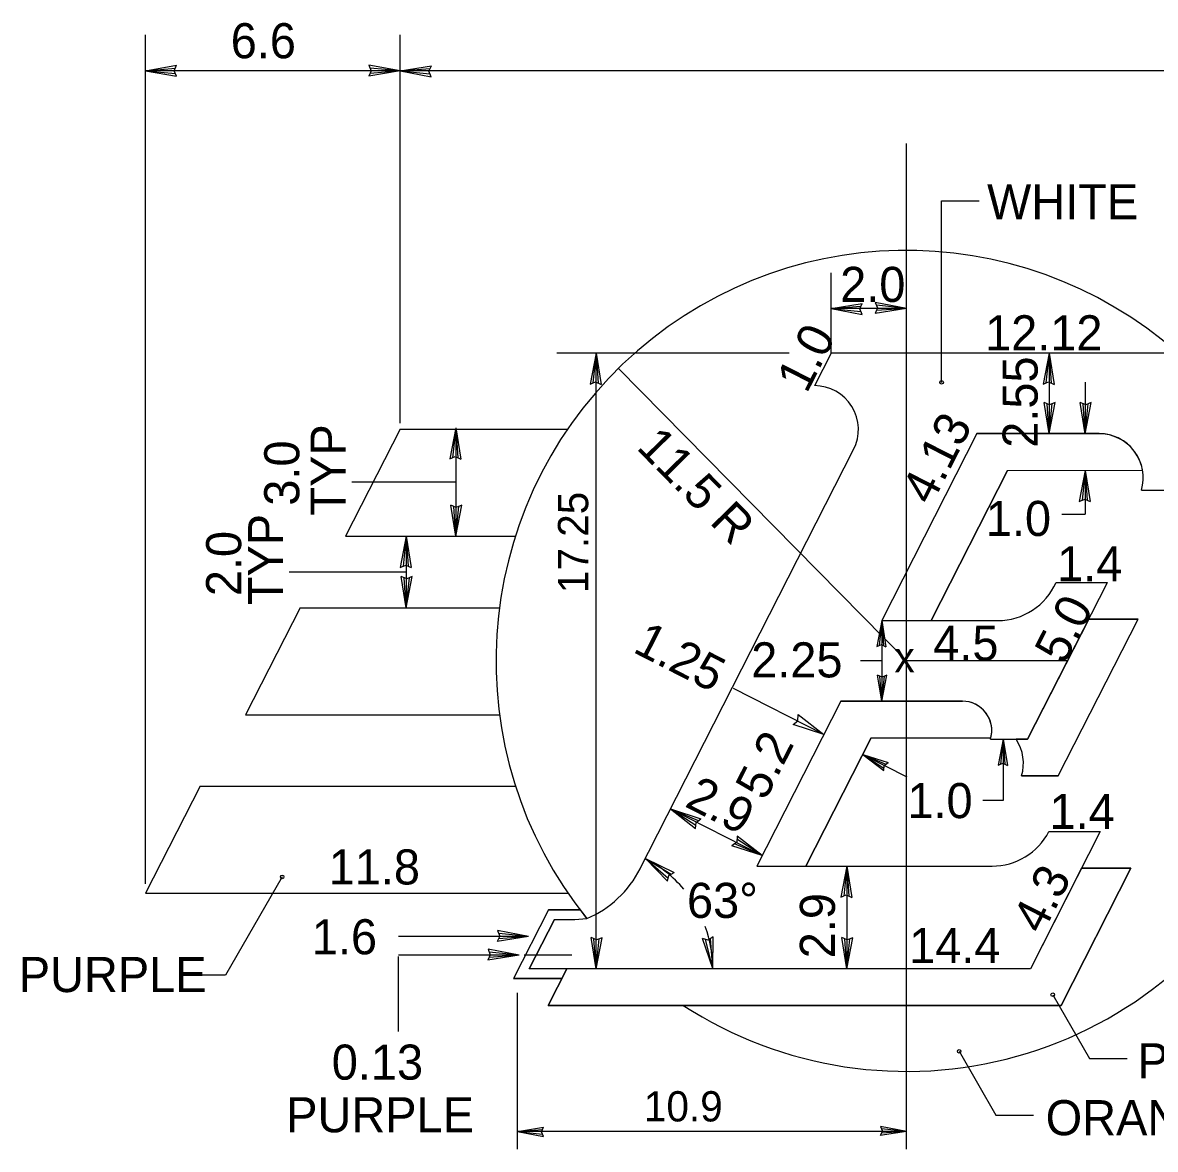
# Model space of a CAD drawing. Extents: x 10268197 to 10269179, y 2141503 to 2142677.
# Drawn here: x 10268648.48 to 10268671.08, y 2142115.25 to 2142137.72 of the extents above; entities that cross this region are included whole.
import ezdxf

# ---------------------------------------------------------------- set-up
doc = ezdxf.new("R2010")
doc.units = 0
for name, color, linetype in [('1', 7, 'Continuous'), ('2', 7, 'Continuous'), ('20', 7, 'Continuous'), ('21', 7, 'Continuous'), ('3', 7, 'Continuous'), ('52', 7, 'Continuous')]:
    doc.layers.add(name, color=color, linetype=linetype)

msp = doc.modelspace()

# ---------------------------------------------------------------- linework, layer by layer
at = {"layer": '1'}
for p, q in [((10268666.115, 2142124.99), (10268666.116, 2142135.313)), ((10268664.613, 2142131.13), (10268664.281, 2142130.479)), ((10268673.238, 2142131.13), (10268664.613, 2142131.13)), ((10268666.115, 2142124.99), (10268660.37, 2142130.823)), ((10268656.016, 2142129.611), (10268654.928, 2142127.475)), ((10268656.016, 2142129.611), (10268659.357, 2142129.611)), ((10268667.523, 2142129.523), (10268665.624, 2142125.794)), ((10268667.523, 2142129.523), (10268665.624, 2142125.794)), ((10268667.523, 2142129.523), (10268669.963, 2142129.523)), ((10268669.963, 2142129.523), (10268667.523, 2142129.523)), ((10268660.785, 2142120.807), (10268665.064, 2142129.204)), ((10268668.135, 2142128.791), (10268666.608, 2142125.794)), ((10268666.608, 2142125.794), (10268668.135, 2142128.791)), ((10268668.135, 2142128.791), (10268670.829, 2142128.792)), ((10268668.135, 2142128.791), (10268670.829, 2142128.792)), ((10268657.126, 2142128.557), (10268655.055, 2142128.557)), ((10268670.804, 2142128.395), (10268671.844, 2142128.396)), ((10268654.928, 2142127.475), (10268658.315, 2142127.475)), ((10268656.138, 2142126.763), (10268653.801, 2142126.763)), ((10268668.534, 2142123.427), (10268670.127, 2142126.554)), ((10268669.102, 2142126.554), (10268670.127, 2142126.554)), ((10268654.02, 2142126.051), (10268652.931, 2142123.916)), ((10268654.02, 2142126.051), (10268657.998, 2142126.051)), ((10268665.624, 2142125.794), (10268667.937, 2142125.794)), ((10268665.624, 2142125.794), (10268666.608, 2142125.794)), ((10268669.754, 2142125.822), (10268668.534, 2142123.427)), ((10268669.146, 2142122.696), (10268670.739, 2142125.823)), ((10268669.146, 2142122.696), (10268670.739, 2142125.823)), ((10268669.754, 2142125.822), (10268670.739, 2142125.823)), ((10268670.739, 2142125.823), (10268669.754, 2142125.822)), ((10268665.624, 2142124.99), (10268665.199, 2142124.99)), ((10268666.116, 2142115.249), (10268666.115, 2142124.99)), ((10268669.33, 2142124.99), (10268666.115, 2142124.99)), ((10268664.805, 2142124.186), (10268663.129, 2142120.897)), ((10268664.805, 2142124.186), (10268663.129, 2142120.897)), ((10268664.805, 2142124.186), (10268667.236, 2142124.186)), ((10268667.236, 2142124.186), (10268664.805, 2142124.186)), ((10268652.931, 2142123.916), (10268657.999, 2142123.916)), ((10268665.416, 2142123.455), (10268664.113, 2142120.897)), ((10268664.113, 2142120.897), (10268665.416, 2142123.455)), ((10268665.416, 2142123.455), (10268667.802, 2142123.455)), ((10268665.416, 2142123.455), (10268667.802, 2142123.455)), ((10268667.794, 2142123.427), (10268668.534, 2142123.427)), ((10268668.534, 2142123.427), (10268668.307, 2142123.427)), ((10268669.146, 2142122.696), (10268668.414, 2142122.696)), ((10268668.414, 2142122.696), (10268669.146, 2142122.696)), ((10268652.025, 2142122.492), (10268650.935, 2142120.356)), ((10268652.025, 2142122.492), (10268658.319, 2142122.492)), ((10268669.984, 2142121.585), (10268668.59, 2142118.85)), ((10268668.96, 2142121.585), (10268669.984, 2142121.585)), ((10268663.129, 2142120.897), (10268667.825, 2142120.897)), ((10268663.129, 2142120.897), (10268664.113, 2142120.897)), ((10268669.611, 2142120.854), (10268668.59, 2142118.85)), ((10268670.595, 2142120.854), (10268669.201, 2142118.119)), ((10268669.201, 2142118.119), (10268670.595, 2142120.854)), ((10268669.611, 2142120.854), (10268670.595, 2142120.854)), ((10268670.595, 2142120.854), (10268669.611, 2142120.854)), ((10268650.935, 2142120.356), (10268659.366, 2142120.356)), ((10268668.59, 2142118.85), (10268658.593, 2142118.85)), ((10268658.967, 2142118.119), (10268659.339, 2142118.85)), ((10268659.339, 2142118.85), (10268658.967, 2142118.119)), ((10268668.59, 2142118.85), (10268659.339, 2142118.85)), ((10268659.24, 2142118.655), (10268658.275, 2142118.655)), ((10268658.356, 2142115.249), (10268658.356, 2142118.368)), ((10268669.201, 2142118.119), (10268658.967, 2142118.119)), ((10268658.967, 2142118.119), (10268669.201, 2142118.119))]:
    msp.add_line(p, q, dxfattribs=at)
for centre, radius, start, end in [((10268666.115, 2142124.99), 8.187, 48.5904, 218.8792), ((10268664.282, 2142129.603), 0.877, 333.0033, 90.1042), ((10268669.964, 2142128.645), 0.877, 343.4611, 90), ((10268669.964, 2142128.645), 0.877, 9.5941, 90), ((10268667.937, 2142127.066), 1.272, 270, 336.2493), ((10268667.235, 2142123.602), 0.585, 342.6625, 90), ((10268667.235, 2142123.602), 0.585, 345.5225, 90), ((10268667.574, 2142122.946), 0.877, 343.4611, 33.2756), ((10268667.574, 2142122.946), 0.877, 343.4611, 33.2756), ((10268667.825, 2142122.176), 1.279, 270, 332.5096), ((10268666.115, 2142124.99), 8.187, 237.0648, 334.1734), ((10268658.902, 2142121.815), 2.136, 293.1567, 333.0112)]:
    msp.add_arc(centre, radius, start, end, dxfattribs=at)
at = {"layer": '2'}
for p, q in [((10268658.974, 2142120.028), (10268658.275, 2142118.655)), ((10268658.974, 2142120.028), (10268659.611, 2142120.028)), ((10268659.093, 2142119.833), (10268658.593, 2142118.85))]:
    msp.add_line(p, q, dxfattribs=at)
at = {"layer": '20'}
for p, q in [((10268650.935, 2142120.546), (10268650.935, 2142137.474)), ((10268656.016, 2142130.772), (10268656.015, 2142137.474)), ((10268656.015, 2142136.761), (10268650.935, 2142136.761)), ((10268703.052, 2142136.761), (10268656.015, 2142136.761)), ((10268666.818, 2142134.168), (10268667.568, 2142134.169)), ((10268666.818, 2142130.546), (10268666.818, 2142134.168)), ((10268664.613, 2142131.13), (10268664.613, 2142132.732)), ((10268666.115, 2142132.021), (10268664.613, 2142132.021)), ((10268663.776, 2142131.13), (10268659.144, 2142131.13)), ((10268659.925, 2142118.85), (10268659.925, 2142131.13)), ((10268668.964, 2142131.13), (10268668.964, 2142129.523)), ((10268656.016, 2142129.735), (10268656.016, 2142130.772)), ((10268669.683, 2142130.549), (10268669.683, 2142129.522)), ((10268657.126, 2142129.638), (10268657.126, 2142127.475)), ((10268669.683, 2142128.791), (10268669.683, 2142127.915)), ((10268669.219, 2142127.915), (10268669.683, 2142127.915)), ((10268656.137, 2142127.475), (10268656.138, 2142126.051)), ((10268665.624, 2142125.794), (10268665.625, 2142124.186)), ((10268664.468, 2142123.524), (10268662.668, 2142124.441)), ((10268668.048, 2142123.427), (10268668.048, 2142122.204)), ((10268665.249, 2142123.126), (10268666.124, 2142122.68)), ((10268668.048, 2142122.204), (10268667.64, 2142122.204)), ((10268661.413, 2142122.038), (10268663.237, 2142121.108)), ((10268664.927, 2142120.897), (10268664.927, 2142118.85)), ((10268653.662, 2142120.682), (10268652.53, 2142118.721)), ((10268658.579, 2142119.491), (10268655.981, 2142119.491)), ((10268655.981, 2142117.599), (10268655.981, 2142119.095)), ((10268658.389, 2142119.118), (10268655.982, 2142119.119)), ((10268659.44, 2142119.119), (10268658.493, 2142119.119)), ((10268652.53, 2142118.721), (10268651.78, 2142118.72)), ((10268669.036, 2142118.332), (10268669.771, 2142117.06)), ((10268667.169, 2142117.204), (10268667.903, 2142115.932)), ((10268669.771, 2142117.06), (10268670.52, 2142117.061)), ((10268667.903, 2142115.932), (10268668.653, 2142115.932)), ((10268666.116, 2142115.606), (10268658.356, 2142115.606))]:
    msp.add_line(p, q, dxfattribs=at)
for centre in [(10268666.818, 2142130.546), (10268653.662, 2142120.682), (10268669.036, 2142118.332), (10268667.169, 2142117.204)]:
    msp.add_circle(centre, 0.0356, dxfattribs=at)
for start, end in [(40.0298, 62.999), (0, 19.9667)]:
    msp.add_arc((10268659.788, 2142118.85), 2.465, start, end, dxfattribs=at)
at = {"layer": '21'}
for p, q in [((10268650.935, 2142136.761), (10268651.557, 2142136.871)), ((10268650.935, 2142136.761), (10268651.532, 2142136.814)), ((10268651.509, 2142136.761), (10268651.557, 2142136.871)), ((10268656.015, 2142136.761), (10268655.394, 2142136.871)), ((10268655.394, 2142136.871), (10268655.441, 2142136.761)), ((10268656.015, 2142136.761), (10268655.418, 2142136.814)), ((10268656.015, 2142136.761), (10268656.639, 2142136.861)), ((10268656.59, 2142136.752), (10268656.639, 2142136.861)), ((10268650.935, 2142136.761), (10268651.557, 2142136.652)), ((10268650.935, 2142136.761), (10268651.532, 2142136.709)), ((10268651.557, 2142136.652), (10268651.509, 2142136.761)), ((10268656.015, 2142136.761), (10268655.393, 2142136.652)), ((10268655.441, 2142136.761), (10268655.393, 2142136.652)), ((10268656.015, 2142136.761), (10268655.419, 2142136.709)), ((10268656.015, 2142136.761), (10268656.612, 2142136.803)), ((10268656.015, 2142136.761), (10268656.635, 2142136.641)), ((10268656.015, 2142136.761), (10268656.611, 2142136.699)), ((10268656.635, 2142136.641), (10268656.59, 2142136.752)), ((10268664.613, 2142132.021), (10268665.237, 2142132.12)), ((10268665.187, 2142132.011), (10268665.237, 2142132.12)), ((10268666.115, 2142132.021), (10268665.496, 2142132.141)), ((10268665.496, 2142132.141), (10268665.541, 2142132.031)), ((10268666.115, 2142132.021), (10268665.519, 2142132.083)), ((10268664.613, 2142132.021), (10268665.21, 2142132.063)), ((10268664.613, 2142132.021), (10268665.233, 2142131.9)), ((10268664.613, 2142132.021), (10268665.209, 2142131.959)), ((10268665.233, 2142131.9), (10268665.187, 2142132.011)), ((10268665.541, 2142132.031), (10268665.492, 2142131.922)), ((10268666.115, 2142132.021), (10268665.492, 2142131.922)), ((10268666.115, 2142132.021), (10268665.518, 2142131.979)), ((10268659.925, 2142131.13), (10268659.805, 2142130.51)), ((10268659.925, 2142131.13), (10268659.863, 2142130.534)), ((10268659.925, 2142131.13), (10268660.024, 2142130.506)), ((10268659.925, 2142131.13), (10268659.967, 2142130.533)), ((10268668.964, 2142131.13), (10268668.844, 2142130.51)), ((10268668.964, 2142131.13), (10268668.901, 2142130.534)), ((10268668.964, 2142131.13), (10268669.063, 2142130.506)), ((10268668.964, 2142131.13), (10268669.006, 2142130.533)), ((10268659.805, 2142130.51), (10268659.915, 2142130.556)), ((10268659.915, 2142130.556), (10268660.024, 2142130.506)), ((10268668.844, 2142130.51), (10268668.954, 2142130.556)), ((10268668.954, 2142130.556), (10268669.063, 2142130.506)), ((10268668.964, 2142129.523), (10268668.865, 2142130.146)), ((10268668.974, 2142130.097), (10268668.865, 2142130.146)), ((10268668.964, 2142129.523), (10268668.922, 2142130.12)), ((10268668.964, 2142129.523), (10268669.084, 2142130.142)), ((10268668.964, 2142129.523), (10268669.026, 2142130.119)), ((10268669.084, 2142130.142), (10268668.974, 2142130.097)), ((10268669.683, 2142129.522), (10268669.584, 2142130.146)), ((10268669.693, 2142130.097), (10268669.584, 2142130.146)), ((10268669.683, 2142129.522), (10268669.641, 2142130.12)), ((10268669.683, 2142129.522), (10268669.803, 2142130.142)), ((10268669.683, 2142129.522), (10268669.745, 2142130.118)), ((10268669.803, 2142130.142), (10268669.693, 2142130.097)), ((10268657.126, 2142129.638), (10268657.006, 2142129.018)), ((10268657.126, 2142129.638), (10268657.063, 2142129.042)), ((10268657.126, 2142129.638), (10268657.225, 2142129.014)), ((10268657.126, 2142129.638), (10268657.168, 2142129.041)), ((10268657.006, 2142129.018), (10268657.116, 2142129.064)), ((10268657.116, 2142129.064), (10268657.225, 2142129.014)), ((10268669.683, 2142128.791), (10268669.563, 2142128.172)), ((10268669.683, 2142128.791), (10268669.621, 2142128.195)), ((10268669.683, 2142128.791), (10268669.782, 2142128.168)), ((10268669.683, 2142128.791), (10268669.725, 2142128.194)), ((10268657.126, 2142127.475), (10268657.027, 2142128.099)), ((10268657.136, 2142128.049), (10268657.027, 2142128.099)), ((10268657.126, 2142127.475), (10268657.084, 2142128.072)), ((10268657.126, 2142127.475), (10268657.247, 2142128.095)), ((10268657.126, 2142127.475), (10268657.188, 2142128.071)), ((10268657.247, 2142128.095), (10268657.136, 2142128.049)), ((10268669.563, 2142128.172), (10268669.673, 2142128.217)), ((10268669.673, 2142128.217), (10268669.782, 2142128.168)), ((10268656.137, 2142127.475), (10268656.017, 2142126.855)), ((10268656.137, 2142127.475), (10268656.075, 2142126.879)), ((10268656.137, 2142127.475), (10268656.236, 2142126.852)), ((10268656.137, 2142127.475), (10268656.179, 2142126.878)), ((10268656.017, 2142126.855), (10268656.127, 2142126.901)), ((10268656.127, 2142126.901), (10268656.236, 2142126.852)), ((10268656.138, 2142126.051), (10268656.039, 2142126.675)), ((10268656.148, 2142126.625), (10268656.039, 2142126.675)), ((10268656.138, 2142126.051), (10268656.096, 2142126.648)), ((10268656.138, 2142126.051), (10268656.258, 2142126.671)), ((10268656.138, 2142126.051), (10268656.2, 2142126.647)), ((10268656.258, 2142126.671), (10268656.148, 2142126.625)), ((10268665.624, 2142125.794), (10268665.524, 2142125.277)), ((10268665.624, 2142125.794), (10268665.573, 2142125.297)), ((10268665.624, 2142125.794), (10268665.707, 2142125.273)), ((10268665.624, 2142125.794), (10268665.659, 2142125.296)), ((10268665.524, 2142125.277), (10268665.617, 2142125.315)), ((10268665.617, 2142125.315), (10268665.707, 2142125.273)), ((10268665.625, 2142124.186), (10268665.542, 2142124.707)), ((10268665.633, 2142124.665), (10268665.542, 2142124.707)), ((10268665.625, 2142124.186), (10268665.589, 2142124.685)), ((10268665.625, 2142124.186), (10268665.725, 2142124.703)), ((10268665.625, 2142124.186), (10268665.677, 2142124.683)), ((10268665.725, 2142124.703), (10268665.633, 2142124.665)), ((10268668.048, 2142123.427), (10268667.948, 2142122.91)), ((10268668.048, 2142123.427), (10268667.996, 2142122.93)), ((10268668.048, 2142123.427), (10268668.131, 2142122.906)), ((10268668.048, 2142123.427), (10268668.083, 2142122.929)), ((10268665.249, 2142123.126), (10268665.75, 2142122.964)), ((10268665.249, 2142123.126), (10268665.664, 2142122.802)), ((10268665.249, 2142123.126), (10268665.668, 2142122.854)), ((10268665.249, 2142123.126), (10268665.709, 2142122.931)), ((10268665.664, 2142122.802), (10268665.672, 2142122.901)), ((10268665.672, 2142122.901), (10268665.75, 2142122.964)), ((10268667.948, 2142122.91), (10268668.04, 2142122.948)), ((10268668.04, 2142122.948), (10268668.131, 2142122.906)), ((10268661.413, 2142122.038), (10268662.013, 2142121.843)), ((10268661.413, 2142122.038), (10268661.91, 2142121.65)), ((10268661.413, 2142122.038), (10268661.915, 2142121.712)), ((10268661.413, 2142122.038), (10268661.964, 2142121.804)), ((10268661.91, 2142121.65), (10268661.92, 2142121.769)), ((10268661.92, 2142121.769), (10268662.013, 2142121.843)), ((10268662.739, 2142121.497), (10268662.73, 2142121.378)), ((10268663.237, 2142121.108), (10268662.739, 2142121.497)), ((10268662.73, 2142121.378), (10268662.636, 2142121.304)), ((10268663.237, 2142121.108), (10268662.636, 2142121.304)), ((10268663.237, 2142121.108), (10268662.686, 2142121.342)), ((10268663.237, 2142121.108), (10268662.734, 2142121.435)), ((10268660.911, 2142121.046), (10268661.48, 2142120.771)), ((10268660.911, 2142121.046), (10268661.351, 2142120.594)), ((10268660.911, 2142121.046), (10268661.365, 2142120.655)), ((10268660.911, 2142121.046), (10268661.425, 2142120.74)), ((10268661.377, 2142120.71), (10268661.48, 2142120.771)), ((10268664.927, 2142120.897), (10268664.806, 2142120.277)), ((10268664.927, 2142120.897), (10268664.865, 2142120.301)), ((10268664.927, 2142120.897), (10268665.026, 2142120.273)), ((10268664.927, 2142120.897), (10268664.969, 2142120.299)), ((10268661.351, 2142120.594), (10268661.377, 2142120.71)), ((10268664.806, 2142120.277), (10268664.917, 2142120.322)), ((10268664.917, 2142120.322), (10268665.026, 2142120.273)), ((10268658.004, 2142119.501), (10268657.955, 2142119.392)), ((10268658.579, 2142119.491), (10268657.955, 2142119.392)), ((10268658.579, 2142119.491), (10268657.959, 2142119.611)), ((10268657.959, 2142119.611), (10268658.004, 2142119.501)), ((10268658.579, 2142119.491), (10268657.981, 2142119.449)), ((10268658.579, 2142119.491), (10268657.983, 2142119.553)), ((10268659.925, 2142118.85), (10268659.826, 2142119.474)), ((10268659.935, 2142119.424), (10268659.826, 2142119.474)), ((10268659.925, 2142118.85), (10268659.883, 2142119.447)), ((10268659.925, 2142118.85), (10268660.045, 2142119.47)), ((10268659.925, 2142118.85), (10268659.987, 2142119.446)), ((10268660.045, 2142119.47), (10268659.935, 2142119.424)), ((10268662.253, 2142118.854), (10268662.047, 2142119.451)), ((10268662.163, 2142119.421), (10268662.047, 2142119.451)), ((10268662.253, 2142118.854), (10268662.108, 2142119.435)), ((10268662.264, 2142119.485), (10268662.163, 2142119.421)), ((10268662.253, 2142118.854), (10268662.211, 2142119.452)), ((10268662.253, 2142118.854), (10268662.264, 2142119.485)), ((10268664.927, 2142118.85), (10268664.828, 2142119.474)), ((10268664.937, 2142119.424), (10268664.828, 2142119.474)), ((10268664.927, 2142118.85), (10268664.885, 2142119.447)), ((10268664.927, 2142118.85), (10268665.047, 2142119.47)), ((10268664.927, 2142118.85), (10268664.989, 2142119.446)), ((10268665.047, 2142119.47), (10268664.937, 2142119.424)), ((10268658.389, 2142119.118), (10268657.769, 2142119.239)), ((10268657.769, 2142119.239), (10268657.815, 2142119.128)), ((10268657.815, 2142119.128), (10268657.765, 2142119.02)), ((10268658.389, 2142119.118), (10268657.765, 2142119.02)), ((10268658.389, 2142119.118), (10268657.792, 2142119.077)), ((10268658.389, 2142119.118), (10268657.793, 2142119.181)), ((10268658.356, 2142115.606), (10268658.876, 2142115.689)), ((10268658.356, 2142115.606), (10268658.854, 2142115.641)), ((10268658.356, 2142115.606), (10268658.873, 2142115.506)), ((10268658.356, 2142115.606), (10268658.853, 2142115.554)), ((10268658.835, 2142115.598), (10268658.876, 2142115.689)), ((10268658.873, 2142115.506), (10268658.835, 2142115.598)), ((10268665.637, 2142115.614), (10268665.595, 2142115.524)), ((10268666.116, 2142115.606), (10268665.595, 2142115.524)), ((10268666.116, 2142115.606), (10268665.598, 2142115.707)), ((10268665.598, 2142115.707), (10268665.637, 2142115.614)), ((10268666.116, 2142115.606), (10268665.617, 2142115.571)), ((10268666.116, 2142115.606), (10268665.618, 2142115.658))]:
    msp.add_line(p, q, dxfattribs=at)
at = {"layer": '3'}
for p, q in [((10268659.093, 2142119.833), (10268659.503, 2142119.833)), ((10268659.503, 2142119.833), (10268659.742, 2142119.852))]:
    msp.add_line(p, q, dxfattribs=at)
msp.add_lwpolyline([(10268659.611, 2142120.028), (10268658.974, 2142120.028), (10268658.275, 2142118.655), (10268659.24, 2142118.655), (10268659.339, 2142118.85), (10268658.593, 2142118.85), (10268659.093, 2142119.833), (10268659.503, 2142119.833), (10268659.742, 2142119.852)], close=True, dxfattribs=at)
at = {"layer": '52'}
msp.add_lwpolyline([(10268664.468, 2142123.524), (10268663.856, 2142123.723), (10268663.948, 2142123.798), (10268663.96, 2142123.919)], close=True, dxfattribs=at)

# ---------------------------------------------------------------- texts
at = {"layer": '1'}
msp.add_text('x', height=0.604, dxfattribs=at).set_placement((10268665.878, 2142124.763))
at = {"layer": '20'}
for s, height, p in [('6.6', 0.7, (10268652.636, 2142137.01)), ('WHITE', 0.7, (10268667.725, 2142133.798)), ('2.0', 0.7, (10268664.795, 2142132.15)), ('12.12', 0.7, (10268667.686, 2142131.184)), ('1.0', 0.7, (10268667.701, 2142127.482)), ('1.4', 0.7, (10268669.123, 2142126.578)), ('4.5', 0.7, (10268666.652, 2142124.996)), ('1.0', 0.7, (10268666.136, 2142121.854)), ('1.4', 0.7, (10268668.973, 2142121.639)), ('11.8', 0.7, (10268654.59, 2142120.531)), ('63°', 0.7, (10268661.739, 2142119.864)), ('1.6', 0.7, (10268654.254, 2142119.138)), ('14.4', 0.7, (10268666.172, 2142118.964)), ('PURPLE', 0.7, (10268648.408, 2142118.385)), ('0.13', 0.7, (10268654.652, 2142116.638)), ('PURPLE', 0.7, (10268670.725, 2142116.663)), ('PURPLE', 0.7, (10268653.743, 2142115.588)), ('10.9', 0.6037, (10268660.88, 2142115.805)), ('ORANGE', 0.7, (10268668.895, 2142115.53))]:
    msp.add_text(s, height=height, dxfattribs=at).set_placement(p)
for s, height, rotation, p in [('1.0', 0.7, 62.9854, (10268664.126, 2142130.306)), ('2.55', 0.7, 90, (10268668.735, 2142129.241)), ('4.13', 0.7, 63.012, (10268666.615, 2142128.072)), ('TYP', 0.7, 90, (10268654.929, 2142127.889)), ('11.5 R', 0.7, 314.5624, (10268660.712, 2142129.23)), ('3.0', 0.7, 90, (10268654.004, 2142128.086)), ('17.25', 0.6037, 90, (10268659.768, 2142126.343)), ('TYP', 0.7, 90, (10268653.682, 2142126.101)), ('2.0', 0.7, 90, (10268652.845, 2142126.281)), ('5.0', 0.7, 63.0087, (10268669.268, 2142124.897)), ('1.25', 0.7, 333.0041, (10268660.636, 2142125.177)), ('2.25', 0.7, 360, (10268663.02, 2142124.661)), ('5.2', 0.7, 63.0001, (10268663.299, 2142122.183)), ('2.9', 0.7, 333.0028, (10268661.672, 2142122.098)), ('4.3', 0.7, 62.9952, (10268668.828, 2142119.515)), ('2.9', 0.7, 90, (10268664.691, 2142119.059))]:
    msp.add_text(s, height=height, rotation=rotation, dxfattribs=at).set_placement(p)

doc.saveas('drawing.dxf')
